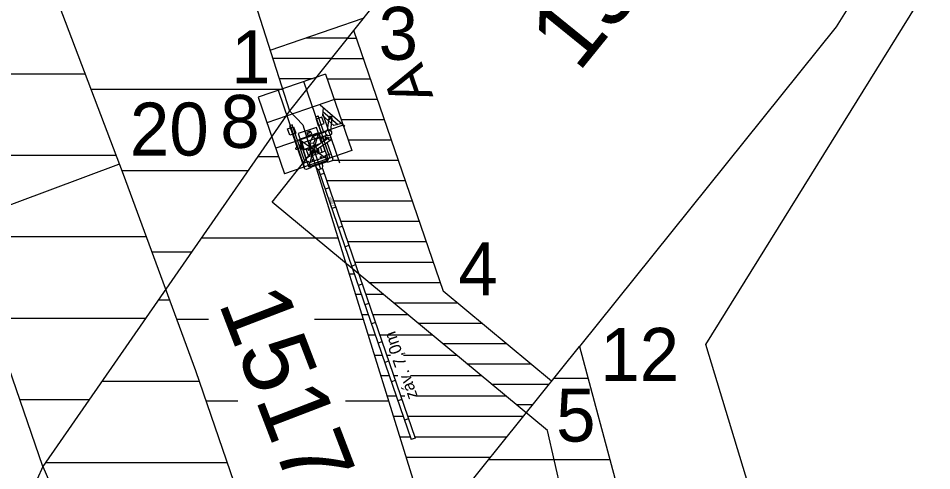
# Model space of a CAD drawing. Extents: x -553916 to -552953, y -1067469 to -1066637.
# Drawn here: x -553520.01 to -553497.58, y -1066979.8 to -1066968.69 of the extents above; entities that cross this region are included whole.
import ezdxf

# ---------------------------------------------------------------- set-up
doc = ezdxf.new("R2010")
doc.units = 0
for name, color, linetype in [('Hranice parcel', 7, 'Continuous'), ('Kolej', 7, 'Continuous'), ('Nová kabelizace', 7, 'Continuous'), ('nové prvky ZZ', 7, 'Continuous'), ('Parcelní čísla', 7, 'Continuous'), ('Propustek', 7, 'Continuous'), ('Vrstva 1', 7, 'Continuous'), ('Vrstva 58', 7, 'Continuous'), ('Vrstva 60', 7, 'Continuous')]:
    doc.layers.add(name, color=color, linetype=linetype)

msp = doc.modelspace()

# ---------------------------------------------------------------- linework, layer by layer
at = {"layer": 'Hranice parcel'}
for p, q in [((-553486.47, -1066947.45), (-553499.93, -1066968.9)), ((-553499.93, -1066968.9), (-553506.23, -1066976.75)), ((-553519.4, -1066979.7), (-553528.66, -1067000.03))]:
    msp.add_line(p, q, dxfattribs=at)
for points in [[(-553489.9, -1066939.2), (-553506.21, -1066961.59), (-553507.62, -1066963.64), (-553510.49, -1066967.37), (-553513.35, -1066970.96)], [(-553481.25, -1066991.64), (-553501.02, -1066983.66), (-553503.13, -1066976.7), (-553485.37, -1066948.09)]]:
    msp.add_lwpolyline(points, dxfattribs=at)
at = {"layer": 'Kolej'}
msp.add_lwpolyline([(-553503.324, -1067065.808), (-553502.678, -1067054.027), (-553502.762, -1067041.504), (-553503.626, -1067029.057), (-553504.756, -1067019.974), (-553506.183, -1067011.388), (-553508.328, -1067001.388), (-553510.948, -1066991.622), (-553512.921, -1066985.291), (-553515.647, -1066977.347), (-553517.422, -1066972.53), (-553519.157, -1066967.95), (-553522.886, -1066958.375), (-553529.101, -1066942.549), (-553538.686, -1066918.107), (-553542.908, -1066907.329), (-553546.692, -1066897.676), (-553555.025, -1066876.441), (-553564.644, -1066851.894), (-553574.241, -1066827.427), (-553583.19, -1066804.618)], dxfattribs=at)
at = {"layer": 'Nová kabelizace'}
msp.add_line((-553505.478, -1066985.448), (-553507.017, -1066978.813), dxfattribs=at)
for points in [[(-553507.017, -1066978.813), (-553513.769, -1066973.209), (-553512.749, -1066971.917)], [(-553506.913, -1066977.6), (-553509.575, -1066975.39)]]:
    msp.add_lwpolyline(points, dxfattribs=at)
at = {"layer": 'nové prvky ZZ'}
for p, q in [((-553512.461, -1066970.063), (-553514.116, -1066970.631)), ((-553512.349, -1066972.124), (-553512.993, -1066970.246)), ((-553512.461, -1066970.063), (-553511.816, -1066971.941)), ((-553512.975, -1066972.339), (-553513.62, -1066970.461)), ((-553514.116, -1066970.631), (-553513.471, -1066972.509)), ((-553512.246, -1066970.689), (-553513.901, -1066971.257)), ((-553512.595, -1066970.814), (-553511.991, -1066971.338)), ((-553512.52, -1066970.88), (-553512.54, -1066971.079)), ((-553512.7, -1066971.109), (-553512.644, -1066971.09)), ((-553512.56, -1066971.518), (-553512.7, -1066971.109)), ((-553512.504, -1066971.499), (-553512.644, -1066971.09)), ((-553512.54, -1066971.079), (-553512.261, -1066971.321)), ((-553512.53, -1066970.979), (-553512.163, -1066971.297)), ((-553512.528, -1066971.045), (-553512.119, -1066972.237)), ((-553512.385, -1066971.135), (-553512.421, -1066971.443)), ((-553512.293, -1066971.076), (-553512.4, -1066971.2)), ((-553512.355, -1066971.139), (-553512.338, -1066971.137)), ((-553512.345, -1066971.146), (-553512.348, -1066971.13)), ((-553512.306, -1066971.145), (-553512.341, -1066971.451)), ((-553512.031, -1066971.315), (-553513.686, -1066971.883)), ((-553513.282, -1066971.308), (-553513.337, -1066971.328)), ((-553512.971, -1066972.394), (-553513.337, -1066971.328)), ((-553512.964, -1066972.234), (-553513.282, -1066971.308)), ((-553512.066, -1066971.273), (-553512.261, -1066971.321)), ((-553513.106, -1066971.666), (-553512.624, -1066971.499)), ((-553513.05, -1066971.646), (-553512.624, -1066971.499)), ((-553512.91, -1066971.521), (-553512.912, -1066971.522)), ((-553512.875, -1066972.337), (-553512.624, -1066971.499)), ((-553512.775, -1066971.592), (-553512.853, -1066971.748)), ((-553512.453, -1066971.481), (-553512.775, -1066971.592)), ((-553512.775, -1066971.592), (-553512.713, -1066971.663)), ((-553512.713, -1066971.663), (-553512.427, -1066971.565)), ((-553512.393, -1066972.17), (-553512.624, -1066971.499)), ((-553512.445, -1066971.67), (-553512.476, -1066971.582)), ((-553512.875, -1066972.337), (-553513.105, -1066971.665)), ((-553513.105, -1066971.665), (-553512.393, -1066972.17)), ((-553513.079, -1066971.816), (-553513.058, -1066971.878)), ((-553513.056, -1066971.755), (-553513.007, -1066971.899)), ((-553513.043, -1066971.751), (-553512.993, -1066971.897)), ((-553512.853, -1066971.748), (-553512.811, -1066971.868)), ((-553512.853, -1066971.748), (-553512.757, -1066971.756)), ((-553512.759, -1066971.82), (-553512.743, -1066971.808)), ((-553512.713, -1066971.663), (-553512.757, -1066971.756)), ((-553512.757, -1066971.756), (-553512.734, -1066971.823)), ((-553512.743, -1066971.808), (-553512.73, -1066971.829)), ((-553512.736, -1066971.818), (-553512.591, -1066971.768)), ((-553512.731, -1066971.828), (-553512.628, -1066971.793)), ((-553512.377, -1066971.624), (-553512.717, -1066971.853)), ((-553512.336, -1066971.681), (-553512.677, -1066971.91)), ((-553512.609, -1066971.628), (-553512.567, -1066971.752)), ((-553512.587, -1066971.659), (-553512.557, -1066971.745)), ((-553512.557, -1066971.744), (-553512.552, -1066971.733)), ((-553512.496, -1066971.704), (-553512.531, -1066971.601)), ((-553512.47, -1066971.957), (-553512.522, -1066971.806)), ((-553512.506, -1066971.675), (-553512.469, -1066971.663)), ((-553512.383, -1066972.035), (-553512.472, -1066971.773)), ((-553512.469, -1066971.663), (-553512.461, -1066971.657)), ((-553512.461, -1066971.657), (-553512.454, -1066971.644)), ((-553512.422, -1066971.607), (-553512.434, -1066971.611)), ((-553512.411, -1066971.64), (-553512.423, -1066971.644)), ((-553512.421, -1066971.611), (-553512.422, -1066971.607)), ((-553512.278, -1066972.156), (-553512.422, -1066971.738)), ((-553512.414, -1066971.609), (-553512.421, -1066971.611)), ((-553512.414, -1066971.609), (-553512.405, -1066971.633)), ((-553512.405, -1066971.633), (-553512.412, -1066971.636)), ((-553512.412, -1066971.636), (-553512.411, -1066971.64)), ((-553511.816, -1066971.941), (-553513.471, -1066972.509)), ((-553513.201, -1066971.879), (-553513.194, -1066971.877)), ((-553513.201, -1066971.879), (-553513.192, -1066971.903)), ((-553513.195, -1066971.873), (-553513.183, -1066971.869)), ((-553513.194, -1066971.877), (-553513.195, -1066971.873)), ((-553513.192, -1066971.903), (-553513.185, -1066971.901)), ((-553513.185, -1066971.901), (-553513.184, -1066971.905)), ((-553513.184, -1066971.905), (-553513.172, -1066971.901)), ((-553513.134, -1066971.888), (-553513.147, -1066971.882)), ((-553513.124, -1066971.888), (-553513.134, -1066971.888)), ((-553513.087, -1066971.875), (-553513.124, -1066971.888)), ((-553513.021, -1066971.894), (-553512.944, -1066972.12)), ((-553513.007, -1066971.899), (-553512.995, -1066971.912)), ((-553512.995, -1066971.912), (-553512.977, -1066971.913)), ((-553512.993, -1066971.897), (-553512.98, -1066971.902)), ((-553512.98, -1066971.902), (-553512.819, -1066971.846)), ((-553512.977, -1066971.913), (-553512.815, -1066971.857)), ((-553512.871, -1066972.089), (-553512.936, -1066971.899)), ((-553512.907, -1066971.888), (-553512.898, -1066971.914)), ((-553512.898, -1066971.914), (-553512.891, -1066971.922)), ((-553512.895, -1066971.884), (-553512.885, -1066971.916)), ((-553512.891, -1066971.922), (-553512.882, -1066971.927)), ((-553512.885, -1066971.916), (-553512.876, -1066971.916)), ((-553512.882, -1066971.927), (-553512.873, -1066971.927)), ((-553512.876, -1066971.916), (-553512.85, -1066971.907)), ((-553512.873, -1066971.927), (-553512.84, -1066971.916)), ((-553512.871, -1066972.089), (-553512.546, -1066971.978)), ((-553512.851, -1066971.92), (-553512.83, -1066971.981)), ((-553512.842, -1066971.911), (-553512.819, -1066971.977)), ((-553512.8, -1066971.856), (-553512.763, -1066971.83)), ((-553512.717, -1066971.906), (-553512.782, -1066971.929)), ((-553512.769, -1066971.848), (-553512.757, -1066971.84)), ((-553512.76, -1066971.885), (-553512.738, -1066971.95)), ((-553512.745, -1066971.916), (-553512.754, -1066971.919)), ((-553512.748, -1066971.922), (-553512.751, -1066971.913)), ((-553512.749, -1066971.917), (-553512.585, -1066972.397)), ((-553512.73, -1066971.829), (-553512.746, -1066971.84)), ((-553512.731, -1066971.83), (-553512.725, -1066971.849)), ((-553512.71, -1066971.986), (-553512.674, -1066971.964)), ((-553512.693, -1066971.963), (-553512.681, -1066971.955)), ((-553512.658, -1066971.931), (-553512.677, -1066971.944)), ((-553512.673, -1066971.908), (-553512.668, -1066971.925)), ((-553512.664, -1066971.964), (-553512.645, -1066971.951)), ((-553512.663, -1066971.901), (-553512.656, -1066971.921)), ((-553512.645, -1066971.951), (-553512.658, -1066971.931)), ((-553512.546, -1066971.978), (-553512.589, -1066971.851)), ((-553512.541, -1066971.976), (-553512.546, -1066971.978)), ((-553512.539, -1066971.981), (-553512.541, -1066971.976)), ((-553512.47, -1066971.957), (-553512.539, -1066971.981)), ((-553512.468, -1066972.064), (-553512.349, -1066972.023)), ((-553512.349, -1066972.023), (-553512.319, -1066972.037)), ((-553512.998, -1066972.246), (-553513.012, -1066972.274)), ((-553512.879, -1066972.205), (-553512.998, -1066972.246)), ((-553512.944, -1066972.12), (-553512.874, -1066972.096)), ((-553512.867, -1066972.238), (-553512.879, -1066972.205)), ((-553512.876, -1066972.091), (-553512.871, -1066972.089)), ((-553512.874, -1066972.096), (-553512.876, -1066972.091)), ((-553512.875, -1066972.337), (-553512.393, -1066972.17)), ((-553512.548, -1066972.254), (-553512.705, -1066972.308)), ((-553512.456, -1066972.097), (-553512.468, -1066972.064)), ((-553512.418, -1066972.209), (-553512.412, -1066972.226)), ((-553512.412, -1066972.226), (-553512.293, -1066972.185)), ((-553512.293, -1066972.185), (-553512.278, -1066972.156)), ((-553512.942, -1066972.408), (-553512.971, -1066972.394)), ((-553512.823, -1066972.367), (-553512.942, -1066972.408)), ((-553512.829, -1066972.35), (-553512.823, -1066972.367)), ((-553512.538, -1066972.381), (-553512.632, -1066972.413)), ((-553512.632, -1066972.413), (-553510.36, -1066979.034)), ((-553512.593, -1066972.525), (-553512.499, -1066972.493)), ((-553512.538, -1066972.381), (-553510.266, -1066979.002)), ((-553512.375, -1066972.854), (-553512.469, -1066972.886)), ((-553512.213, -1066973.327), (-553512.307, -1066973.359)), ((-553512.051, -1066973.8), (-553512.145, -1066973.832)), ((-553511.889, -1066974.273), (-553511.983, -1066974.305)), ((-553511.726, -1066974.746), (-553511.82, -1066974.778)), ((-553511.564, -1066975.218), (-553511.658, -1066975.251)), ((-553511.402, -1066975.691), (-553511.496, -1066975.724)), ((-553511.239, -1066976.164), (-553511.333, -1066976.197)), ((-553511.077, -1066976.637), (-553511.171, -1066976.67)), ((-553510.915, -1066977.11), (-553511.009, -1066977.142)), ((-553510.753, -1066977.583), (-553510.847, -1066977.615)), ((-553510.59, -1066978.056), (-553510.684, -1066978.088)), ((-553510.428, -1066978.529), (-553510.522, -1066978.561)), ((-553510.266, -1066979.002), (-553510.36, -1066979.034))]:
    msp.add_line(p, q, dxfattribs=at)
for points in [[(-553512.696, -1066971.168), (-553512.643, -1066971.323), (-553512.497, -1066971.273), (-553512.55, -1066971.118)], [(-553513.248, -1066971.357), (-553513.195, -1066971.513), (-553513.341, -1066971.563), (-553513.395, -1066971.408)], [(-553513.136, -1066971.523), (-553513.056, -1066971.755), (-553512.606, -1066971.601), (-553512.686, -1066971.369)], [(-553513.111, -1066971.805), (-553513.076, -1066971.908), (-553513.063, -1066971.903), (-553513.098, -1066971.801)], [(-553513.069, -1066971.77), (-553513.053, -1066971.819), (-553513.036, -1066971.813), (-553513.053, -1066971.764)], [(-553512.848, -1066971.904), (-553512.851, -1066971.896), (-553512.833, -1066971.89), (-553512.83, -1066971.898)], [(-553512.811, -1066972.035), (-553512.806, -1066972.05), (-553512.784, -1066972.043), (-553512.789, -1066972.027)], [(-553512.649, -1066971.979), (-553512.644, -1066971.994), (-553512.621, -1066971.987), (-553512.627, -1066971.972)], [(-553512.867, -1066972.238), (-553512.829, -1066972.35), (-553512.418, -1066972.209), (-553512.456, -1066972.097)]]:
    msp.add_lwpolyline(points, close=True, dxfattribs=at)
for points in [[(-553512.869, -1066971.473), (-553512.92, -1066971.491), (-553512.91, -1066971.521), (-553512.858, -1066971.503), (-553512.865, -1066971.484)], [(-553512.912, -1066971.522), (-553512.896, -1066971.57), (-553512.802, -1066971.537), (-553512.82, -1066971.483), (-553512.86, -1066971.497)], [(-553512.865, -1066971.484), (-553512.838, -1066971.475), (-553512.841, -1066971.464), (-553512.869, -1066971.473)], [(-553513.079, -1066971.816), (-553513.091, -1066971.82), (-553513.07, -1066971.882), (-553513.058, -1066971.878)], [(-553513.065, -1066971.783), (-553513.088, -1066971.791), (-553513.079, -1066971.816)], [(-553513.058, -1066971.878), (-553513.049, -1066971.904), (-553513.017, -1066971.893), (-553513.043, -1066971.815)], [(-553512.754, -1066971.845), (-553512.772, -1066971.818), (-553512.764, -1066971.813), (-553512.743, -1066971.845)], [(-553512.582, -1066971.618), (-553512.57, -1066971.653), (-553512.587, -1066971.659), (-553512.599, -1066971.624)], [(-553512.526, -1066971.724), (-553512.552, -1066971.733), (-553512.579, -1066971.656)], [(-553512.559, -1066971.61), (-553512.551, -1066971.635)], [(-553512.551, -1066971.635), (-553512.534, -1066971.629), (-553512.512, -1066971.691), (-553512.53, -1066971.697)], [(-553512.506, -1066971.711), (-553512.54, -1066971.609), (-553512.53, -1066971.606), (-553512.496, -1066971.704)], [(-553512.53, -1066971.697), (-553512.521, -1066971.721)], [(-553512.44, -1066971.667), (-553512.446, -1066971.669), (-553512.467, -1066971.606), (-553512.458, -1066971.602), (-553512.454, -1066971.614)], [(-553512.454, -1066971.614), (-553512.435, -1066971.607), (-553512.434, -1066971.611)], [(-553512.423, -1066971.644), (-553512.421, -1066971.648), (-553512.44, -1066971.654)], [(-553512.44, -1066971.654), (-553512.436, -1066971.665)], [(-553513.166, -1066971.858), (-553513.185, -1066971.864), (-553513.183, -1066971.869)], [(-553513.172, -1066971.901), (-553513.171, -1066971.905), (-553513.152, -1066971.899)], [(-553513.152, -1066971.899), (-553513.148, -1066971.91), (-553513.139, -1066971.907), (-553513.16, -1066971.843), (-553513.17, -1066971.847), (-553513.166, -1066971.858)], [(-553512.827, -1066971.9), (-553512.828, -1066971.897), (-553512.853, -1066971.906), (-553512.85, -1066971.914), (-553512.828, -1066971.906)], [(-553512.806, -1066971.973), (-553512.846, -1066971.986), (-553512.843, -1066971.995), (-553512.799, -1066971.98), (-553512.799, -1066971.98)], [(-553512.798, -1066971.98), (-553512.835, -1066971.993), (-553512.82, -1066972.038), (-553512.781, -1066972.025), (-553512.796, -1066971.982)], [(-553512.684, -1066971.949), (-553512.666, -1066971.977), (-553512.659, -1066971.971), (-553512.68, -1066971.939)], [(-553512.68, -1066971.94), (-553512.662, -1066971.934)], [(-553512.658, -1066971.932), (-553512.625, -1066971.921), (-553512.628, -1066971.911), (-553512.678, -1066971.928)], [(-553512.66, -1066971.973), (-553512.657, -1066971.982), (-553512.619, -1066971.969), (-553512.634, -1066971.924)], [(-553512.766, -1066972.163), (-553512.761, -1066972.161), (-553512.749, -1066972.197), (-553512.776, -1066972.207), (-553512.789, -1066972.171), (-553512.784, -1066972.169)], [(-553512.784, -1066972.169), (-553512.787, -1066972.161), (-553512.769, -1066972.155), (-553512.766, -1066972.163)], [(-553512.567, -1066972.095), (-553512.562, -1066972.093), (-553512.55, -1066972.129), (-553512.578, -1066972.139), (-553512.59, -1066972.103), (-553512.585, -1066972.101)], [(-553512.585, -1066972.101), (-553512.588, -1066972.093), (-553512.57, -1066972.087), (-553512.567, -1066972.095)], [(-553512.538, -1066972.381), (-553512.526, -1066972.313), (-553512.546, -1066972.253)], [(-553512.632, -1066972.413), (-553512.683, -1066972.367), (-553512.703, -1066972.307)]]:
    msp.add_lwpolyline(points, dxfattribs=at)
for centre, radius in [((-553512.347, -1066971.138), 0.00856), ((-553512.386, -1066971.506), 0.0716), ((-553512.356, -1066971.653), 0.0347), ((-553512.749, -1066971.917), 0.0725)]:
    msp.add_circle(centre, radius, dxfattribs=at)
for centre, radius, start, end in [((-553512.345, -1066971.14), 0.0399, 353.2567, 174.9637), ((-553512.749, -1066971.917), 0.0795, 129.387, 299.921)]:
    msp.add_arc(centre, radius, start, end, dxfattribs=at)
at = {"layer": 'Propustek'}
msp.add_lwpolyline([(-553576.56, -1066984.514), (-553536.119, -1066969.402), (-553529.408, -1066976.709), (-553517.537, -1066972.276)], dxfattribs=at)
at = {"layer": 'Vrstva 1'}
for p, q in [((-553514.13, -1066968.51), (-553513.35, -1066970.96)), ((-553513.823, -1066969.473), (-553511.542, -1066968.69)), ((-553511.774, -1066968.982), (-553509.575, -1066975.39)), ((-553512.948, -1066969.173), (-553511.926, -1066969.173)), ((-553511.929, -1066969.176), (-553511.708, -1066969.176)), ((-553513.76, -1066969.673), (-553512.325, -1066969.673)), ((-553512.327, -1066969.676), (-553511.536, -1066969.676)), ((-553522.825, -1066970.052), (-553518.361, -1066970.052)), ((-553513.601, -1066970.173), (-553512.781, -1066970.173)), ((-553512.422, -1066970.176), (-553511.365, -1066970.176)), ((-553518.218, -1066970.429), (-553513.519, -1066970.429)), ((-553512.25, -1066970.676), (-553511.193, -1066970.676)), ((-553513.35, -1066970.96), (-553519.4, -1066979.7)), ((-553512.079, -1066971.176), (-553511.021, -1066971.176)), ((-553511.907, -1066971.676), (-553510.85, -1066971.676)), ((-553522.025, -1066972.052), (-553517.603, -1066972.052)), ((-553512.289, -1066972.176), (-553510.678, -1066972.176)), ((-553517.46, -1066972.429), (-553514.367, -1066972.429)), ((-553512.437, -1066972.676), (-553510.507, -1066972.676)), ((-553512.265, -1066973.176), (-553510.335, -1066973.176)), ((-553512.093, -1066973.676), (-553510.164, -1066973.676)), ((-553521.338, -1066974.052), (-553516.861, -1066974.052)), ((-553511.922, -1066974.176), (-553509.992, -1066974.176)), ((-553516.722, -1066974.429), (-553515.751, -1066974.429)), ((-553511.75, -1066974.676), (-553509.82, -1066974.676)), ((-553511.886, -1066974.965), (-553511.756, -1066974.965)), ((-553511.4, -1066975.176), (-553509.649, -1066975.176)), ((-553511.73, -1066975.465), (-553511.584, -1066975.465)), ((-553511.479, -1066975.465), (-553511.051, -1066975.465)), ((-553510.797, -1066975.676), (-553509.231, -1066975.676)), ((-553520.656, -1066976.052), (-553516.875, -1066976.052)), ((-553511.575, -1066975.965), (-553511.413, -1066975.965)), ((-553511.308, -1066975.965), (-553510.449, -1066975.965)), ((-553510.195, -1066976.176), (-553508.629, -1066976.176)), ((-553519.4, -1066979.7), (-553520.52, -1066976.45)), ((-553511.42, -1066976.465), (-553511.241, -1066976.465)), ((-553511.136, -1066976.465), (-553509.846, -1066976.465)), ((-553509.91, -1066981.33), (-553506.23, -1066976.75)), ((-553509.592, -1066976.676), (-553508.026, -1066976.676)), ((-553506.23, -1066976.75), (-553504.27, -1066984.05)), ((-553511.265, -1066976.965), (-553511.07, -1066976.965)), ((-553510.965, -1066976.965), (-553510.865, -1066976.965)), ((-553510.547, -1066976.965), (-553509.244, -1066976.965)), ((-553508.99, -1066977.176), (-553507.424, -1066977.176)), ((-553511.11, -1066977.465), (-553510.898, -1066977.465)), ((-553510.793, -1066977.465), (-553510.691, -1066977.465)), ((-553510.374, -1066977.465), (-553508.641, -1066977.465)), ((-553508.387, -1066977.676), (-553506.974, -1066977.676)), ((-553519.968, -1066978.052), (-553518.259, -1066978.052)), ((-553510.954, -1066977.965), (-553510.727, -1066977.965)), ((-553510.622, -1066977.965), (-553510.518, -1066977.965)), ((-553510.2, -1066977.965), (-553508.039, -1066977.965)), ((-553507.784, -1066978.176), (-553507.376, -1066978.176)), ((-553510.799, -1066978.465), (-553510.555, -1066978.465)), ((-553510.45, -1066978.465), (-553507.608, -1066978.465)), ((-553510.644, -1066978.965), (-553510.383, -1066978.965)), ((-553510.278, -1066978.965), (-553508.01, -1066978.965)), ((-553510.489, -1066979.465), (-553508.411, -1066979.465)), ((-553519.4, -1066979.7), (-553514.85, -1066990.05))]:
    msp.add_line(p, q, dxfattribs=at)
msp.add_lwpolyline([(-553513.35, -1066970.96), (-553513.02, -1066971.31), (-553509.91, -1066981.33)], dxfattribs=at)
at = {"layer": 'Vrstva 58'}
for p, q in [((-553514.126, -1066972.081), (-553513.618, -1066972.081)), ((-553515.51, -1066974.081), (-553512.16, -1066974.081)), ((-553516.564, -1066975.603), (-553516.29, -1066975.603)), ((-553516.114, -1066976.081), (-553515.336, -1066976.081)), ((-553512.731, -1066976.081), (-553511.539, -1066976.081)), ((-553517.948, -1066977.603), (-553515.559, -1066977.603)), ((-553506.855, -1066977.528), (-553506.021, -1066977.528)), ((-553515.395, -1066978.081), (-553514.612, -1066978.081)), ((-553511.972, -1066978.081), (-553510.918, -1066978.081)), ((-553519.333, -1066979.603), (-553514.873, -1066979.603)), ((-553508.462, -1066979.528), (-553505.484, -1066979.528))]:
    msp.add_line(p, q, dxfattribs=at)
at = {"layer": 'Vrstva 60'}
for p, q in [((-553511.774, -1066968.982), (-553511.774, -1066968.982)), ((-553513.823, -1066969.473), (-553513.823, -1066969.473)), ((-553513.35, -1066970.96), (-553513.35, -1066970.96)), ((-553513.02, -1066971.31), (-553513.02, -1066971.31)), ((-553509.575, -1066975.391), (-553509.575, -1066975.391)), ((-553506.23, -1066976.75), (-553506.23, -1066976.75)), ((-553506.913, -1066977.6), (-553506.913, -1066977.6)), ((-553519.4, -1066979.7), (-553519.4, -1066979.7))]:
    msp.add_line(p, q, dxfattribs=at)

# ---------------------------------------------------------------- texts
at = {"layer": 'nové prvky ZZ'}
for s, height, rotation, p in [('A', 1.025, 108.8917, (-553509.813, -1066970.609)), ('265', 0.025, 108.9398, (-553512.773, -1066971.948)), ('7,00m', 0.0646, 108.9398, (-553512.243, -1066973.303)), ('záv. 7,0m', 0.3, 109.138, (-553510.19, -1066977.993))]:
    msp.add_text(s, height=height, rotation=rotation, dxfattribs=at).set_placement(p)
at = {"layer": 'Parcelní čísla'}
msp.add_text('1517/1', height=1.7, rotation=51, dxfattribs=at).set_placement((-553506.254, -1066970.044))
at = {"layer": 'Vrstva 1'}
msp.add_text('1517/8', height=1.7, rotation=290.9878, dxfattribs=at).set_placement((-553515.1, -1066975.676))
at = {"layer": 'Vrstva 60'}
for s, p in [('3', (-553511.159, -1066969.71)), ('1', (-553514.78, -1066970.288)), ('8', (-553515.046, -1066971.873)), ('20', (-553517.264, -1066972.061)), ('4', (-553509.203, -1066975.495)), ('12', (-553505.717, -1066977.594)), ('5', (-553506.802, -1066979.086))]:
    msp.add_text(s, height=1.3, dxfattribs=at).set_placement(p)

doc.saveas('drawing.dxf')
